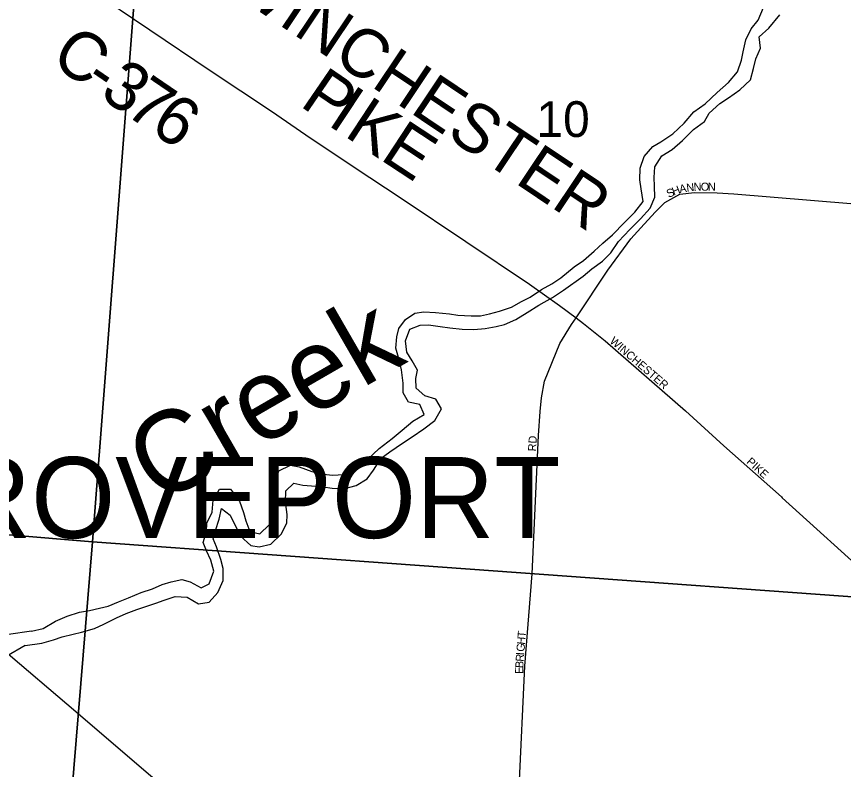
# Model space of a CAD drawing. Extents: x 0 to 34, y 0 to 22.
# Drawn here: x 7.024 to 7.992, y 15.756 to 16.637 of the extents above; entities that cross this region are included whole.
import ezdxf

# ---------------------------------------------------------------- set-up
doc = ezdxf.new("R2010")
doc.units = 0
for name, color, linetype in [('GM_X_City_Street', 7, 'Continuous'), ('GM_X_City_Street_Text', 7, 'Continuous'), ('GM_X_Corporation_Text', 7, 'Continuous'), ('GM_X_County_Road', 7, 'Continuous'), ('GM_X_County_Road_Text', 7, 'Continuous'), ('GM_X_Minor_River', 7, 'Continuous'), ('GM_X_Minor_River_Text', 7, 'Continuous'), ('GM_X_Section', 7, 'Continuous'), ('GM_X_Section_Text', 7, 'Continuous'), ('GM_X_US_Route', 7, 'Continuous')]:
    doc.layers.add(name, color=color, linetype=linetype)

msp = doc.modelspace()

# ---------------------------------------------------------------- linework, layer by layer
at = {"layer": 'GM_X_City_Street'}
for points in [[(7.7547, 16.38954), (7.77139, 16.40792), (7.78273, 16.419), (7.80032, 16.42875), (7.81722, 16.43094), (7.8439, 16.43048), (7.86341, 16.42942), (8.14182, 16.40612)], [(7.68753, 16.27741), (7.71307, 16.25722), (7.80671, 16.1754), (7.85165, 16.13438), (7.91909, 16.07464), (7.92002, 16.07381)], [(7.61133, 15.70908), (7.61237, 15.7349), (7.61879, 15.87676), (7.62739, 15.98461), (7.6347, 16.14646), (7.63698, 16.17463)]]:
    msp.add_lwpolyline(points, dxfattribs=at)
at = {"layer": 'GM_X_County_Road'}
for points in [[(7.10975, 16.66884), (7.25082, 16.57357), (7.32264, 16.52581), (7.36269, 16.4984), (7.41818, 16.46116), (7.47523, 16.42339), (7.62451, 16.32351), (7.65946, 16.29869), (7.67897, 16.28418), (7.68753, 16.27741)], [(7.67897, 16.28418), (7.71594, 16.34009), (7.74303, 16.37669), (7.7547, 16.38954)], [(7.63698, 16.17463), (7.63828, 16.19055), (7.64189, 16.21025), (7.65966, 16.254), (7.67348, 16.27627), (7.67897, 16.28418)], [(7.92002, 16.07381), (8.02963, 15.97446), (8.06308, 15.94263), (8.09822, 15.91233), (8.14483, 15.86599), (8.18695, 15.82554), (8.22682, 15.78847), (8.25305, 15.76356), (8.29526, 15.72367)]]:
    msp.add_lwpolyline(points, dxfattribs=at)
at = {"layer": 'GM_X_Minor_River'}
for points in [[(7.87743, 16.60926), (7.88356, 16.62212), (7.89194, 16.63232), (7.89808, 16.64708)], [(7.89477, 16.59967), (7.89296, 16.61295), (7.90437, 16.62313), (7.91732, 16.63861)], [(7.04191, 15.9178), (7.05527, 15.92097), (7.06969, 15.92923), (7.08334, 15.93522), (7.09773, 15.94007), (7.10947, 15.94189), (7.12121, 15.94448), (7.13143, 15.94707), (7.14356, 15.95193), (7.15532, 15.95679), (7.1701, 15.96277), (7.18336, 15.96725), (7.19474, 15.97211), (7.20497, 15.97546), (7.21746, 15.97804), (7.22728, 15.97533), (7.24009, 15.96842), (7.24957, 15.97292), (7.25496, 15.98768), (7.25164, 16.0006), (7.24641, 16.01164), (7.24269, 16.02153), (7.24655, 16.03441), (7.24698, 16.04389), (7.25312, 16.05676), (7.25434, 16.07079), (7.2616, 16.08365), (7.27446, 16.08395), (7.28496, 16.06984), (7.28979, 16.05653), (7.29238, 16.04665), (7.29722, 16.0341), (7.30892, 16.03137), (7.31996, 16.04193), (7.32647, 16.05517), (7.32693, 16.06883), (7.32701, 16.08135), (7.32669, 16.0916), (7.33093, 16.10523), (7.34459, 16.11198), (7.35479, 16.11002), (7.36988, 16.10462), (7.37969, 16.10152), (7.39405, 16.1003), (7.40729, 16.10097), (7.42169, 16.10544), (7.43424, 16.11751), (7.44832, 16.13146), (7.46352, 16.14313), (7.4753, 16.15293), (7.48784, 16.16348), (7.50113, 16.17099), (7.49591, 16.18278), (7.48269, 16.18552), (7.4767, 16.19656), (7.4764, 16.20794), (7.4746, 16.22351), (7.47091, 16.23795), (7.46795, 16.2486), (7.46916, 16.26187), (7.47149, 16.27172), (7.47912, 16.2823), (7.49013, 16.28982), (7.50073, 16.29128), (7.51434, 16.29044), (7.53059, 16.28882), (7.54041, 16.28724), (7.55629, 16.28639), (7.56688, 16.2867), (7.57748, 16.28891), (7.58922, 16.29188), (7.60324, 16.29673), (7.61501, 16.3031), (7.62525, 16.30835), (7.63854, 16.31738), (7.6503, 16.32376), (7.66093, 16.33091), (7.67651, 16.34371), (7.68753, 16.35124), (7.70007, 16.36217), (7.70996, 16.37159), (7.72137, 16.38139), (7.73545, 16.39572), (7.74762, 16.40779), (7.75715, 16.42025), (7.75497, 16.43507), (7.75353, 16.4457), (7.75399, 16.45936), (7.75861, 16.47299), (7.76852, 16.4847), (7.778, 16.48995), (7.79205, 16.49935), (7.80536, 16.51179), (7.81679, 16.525), (7.8297, 16.53441), (7.84377, 16.54761), (7.85708, 16.55929), (7.86775, 16.57175), (7.87237, 16.58576), (7.87432, 16.59524), (7.87743, 16.60926)], [(7.03446, 15.90095), (7.0539, 15.90354), (7.06766, 15.90761), (7.07751, 15.91097), (7.09039, 15.91431), (7.10024, 15.91652), (7.11539, 15.92061), (7.12639, 15.92585), (7.14118, 15.93335), (7.15255, 15.93821), (7.16506, 15.94307), (7.17567, 15.94642), (7.18704, 15.95053), (7.19689, 15.95388), (7.20978, 15.95836), (7.22377, 15.95752), (7.23695, 15.94946), (7.24944, 15.95167), (7.25972, 15.96299), (7.26586, 15.97699), (7.26595, 15.99103), (7.26336, 16.00167), (7.25816, 16.01612), (7.25444, 16.02563), (7.25714, 16.03548), (7.26138, 16.04874), (7.26411, 16.06124), (7.27427, 16.05321), (7.28622, 16.02885), (7.29825, 16.01777), (7.30807, 16.0162), (7.32171, 16.01953), (7.33388, 16.03122), (7.34039, 16.04408), (7.34083, 16.05432), (7.33902, 16.06838), (7.33911, 16.08166), (7.34862, 16.09071), (7.35919, 16.08836), (7.3694, 16.08754), (7.383, 16.08632), (7.39358, 16.08512), (7.40833, 16.08465), (7.42158, 16.08799), (7.43449, 16.09588), (7.44173, 16.10608), (7.4509, 16.12006), (7.46077, 16.12759), (7.47559, 16.13775), (7.48697, 16.14489), (7.50065, 16.15429), (7.51356, 16.16408), (7.52159, 16.17769), (7.51485, 16.18911), (7.50202, 16.19299), (7.49186, 16.20178), (7.49155, 16.21316), (7.49313, 16.22302), (7.48715, 16.23406), (7.48078, 16.24397), (7.47935, 16.25726), (7.48434, 16.27088), (7.49648, 16.27574), (7.50631, 16.27607), (7.51991, 16.27409), (7.53124, 16.2725), (7.5456, 16.27089), (7.55922, 16.27043), (7.57246, 16.27187), (7.58533, 16.27407), (7.59518, 16.27628), (7.60845, 16.28227), (7.62173, 16.29054), (7.6354, 16.29881), (7.65134, 16.30782), (7.66425, 16.31647), (7.68704, 16.33302), (7.6973, 16.34169), (7.70983, 16.35034), (7.71934, 16.36015), (7.7285, 16.37338), (7.74182, 16.38733), (7.75438, 16.40016), (7.76542, 16.41262), (7.7708, 16.42548), (7.7705, 16.43839), (7.77018, 16.44826), (7.77102, 16.46077), (7.77904, 16.47363), (7.79118, 16.48114), (7.80335, 16.49169), (7.81628, 16.50452), (7.8292, 16.51392), (7.83455, 16.52376), (7.8471, 16.53506), (7.85735, 16.54145), (7.87027, 16.55086), (7.88282, 16.56255), (7.8863, 16.57581), (7.88902, 16.58718), (7.89477, 16.59967)], [(7.04191, 15.9178), (7.01481, 15.91378), (6.99195, 15.89879), (6.98128, 15.89129), (6.97177, 15.88643), (6.96187, 15.88082), (6.94854, 15.87258), (6.93595, 15.86282), (6.92412, 15.85229), (6.91683, 15.84249), (6.91294, 15.83151), (6.91245, 15.82051), (6.91233, 15.80723), (6.91298, 15.7966), (6.91363, 15.78483), (6.91239, 15.7746), (6.90622, 15.76251), (6.89817, 15.75233)], [(7.03446, 15.90095), (7.01306, 15.88837), (7.00239, 15.88125), (6.99096, 15.87451), (6.9807, 15.86967), (6.9708, 15.86443), (6.95862, 15.85732), (6.94643, 15.84983), (6.93614, 15.84271), (6.93035, 15.83061), (6.92986, 15.81961), (6.93011, 15.80633), (6.93148, 15.79114), (6.93288, 15.77899), (6.93012, 15.76687), (6.92015, 15.75367)]]:
    msp.add_lwpolyline(points, dxfattribs=at)
at = {"layer": 'GM_X_Section'}
for points in [[(6.14388, 17.13103), (7.19182, 17.04453), (7.11329, 16.02199), (6.07795, 16.10891)], [(7.19182, 17.04453), (8.21553, 16.97509), (8.13661, 15.94799), (7.11329, 16.02199)], [(6.07795, 16.10891), (7.11329, 16.02199), (7.02886, 14.99926), (6.00383, 15.08864)], [(7.11329, 16.02199), (8.13661, 15.94799), (8.05106, 14.93043), (7.02886, 14.99926)]]:
    msp.add_lwpolyline(points, close=True, dxfattribs=at)
at = {"layer": 'GM_X_US_Route'}
for points in [[(6.8081, 16.06758), (6.92712, 15.96633), (7.01705, 15.8889), (7.08293, 15.83259)], [(7.08293, 15.83259), (7.18095, 15.74882), (7.37841, 15.58015), (7.55258, 15.4305), (7.57219, 15.41283), (7.59328, 15.39487), (7.69808, 15.30689), (7.76574, 15.24904), (7.87803, 15.14924), (7.92702, 15.10025), (7.97091, 15.05625), (8.06972, 14.95196), (8.15383, 14.86262), (8.22164, 14.79709), (8.27046, 14.75714), (8.3091, 14.72804), (8.35168, 14.69861), (8.40281, 14.66737), (8.70762, 14.50067), (9.03085, 14.32306), (9.04058, 14.31774)]]:
    msp.add_lwpolyline(points, dxfattribs=at)

# ---------------------------------------------------------------- texts
at = {"layer": 'GM_X_City_Street_Text'}
for s, rotation, p in [('H', 21.67152, (7.79315, 16.42708)), ('A', 10.83848, (7.80044, 16.43002)), ('N', 7.23073, (7.80847, 16.43157)), ('N', 1.7271, (7.8165, 16.4326)), ('O', 0.02186, (7.82475, 16.43285)), ('N', 0.00001, (7.83308, 16.43285)), ('S', 24.69498, (7.78721, 16.42435)), ('WINCHESTER', 319.11942, (7.71748, 16.25575)), ('RD', 86.98901, (7.63204, 16.12783)), ('PIKE', 317.60121, (7.87751, 16.11489)), ('T', 85.32743, (7.61972, 15.90993)), ('H', 85.31802, (7.61904, 15.90162)), ('G', 85.33065, (7.61837, 15.89332)), ('R', 85.45415, (7.61743, 15.88169)), ('I', 85.31623, (7.61802, 15.88917)), ('E', 89.67212, (7.61703, 15.86772)), ('B', 87.18125, (7.61707, 15.87428))]:
    msp.add_text(s, height=0.00947, rotation=rotation, dxfattribs=at).set_placement(p)
at = {"layer": 'GM_X_Corporation_Text'}
msp.add_text('GROVEPORT', height=0.094697, rotation=0.00001, dxfattribs=at).set_placement((6.85131, 16.02659))
at = {"layer": 'GM_X_County_Road_Text'}
for s, height, rotation, p in [('WINCHESTER', 0.056818, 326.16319, (7.26942, 16.66837)), ('C', 0.05682, 325.56626, (7.06216, 16.58298)), ('3', 0.05682, 325.60915, (7.11994, 16.54338)), ('-', 0.05682, 325.57922, (7.10066, 16.55658)), ('P', 0.05682, 325.61409, (7.35429, 16.53284)), ('7', 0.05682, 325.72724, (7.14893, 16.52354)), ('I', 0.05682, 326.44126, (7.38665, 16.5107)), ('6', 0.05682, 326.41161, (7.17846, 16.50342)), ('K', 0.05682, 326.66693, (7.4063, 16.49766)), ('E', 0.05682, 326.7173, (7.44812, 16.47016))]:
    msp.add_text(s, height=height, rotation=rotation, dxfattribs=at).set_placement(p)
at = {"layer": 'GM_X_Minor_River_Text'}
msp.add_text('Creek', height=0.094693, rotation=30.00029, dxfattribs=at).set_placement((7.19049, 16.06405))
at = {"layer": 'GM_X_Section_Text'}
msp.add_text('10', height=0.041856, rotation=0.00001, dxfattribs=at).set_placement((7.63256, 16.49572))

doc.saveas('drawing.dxf')
